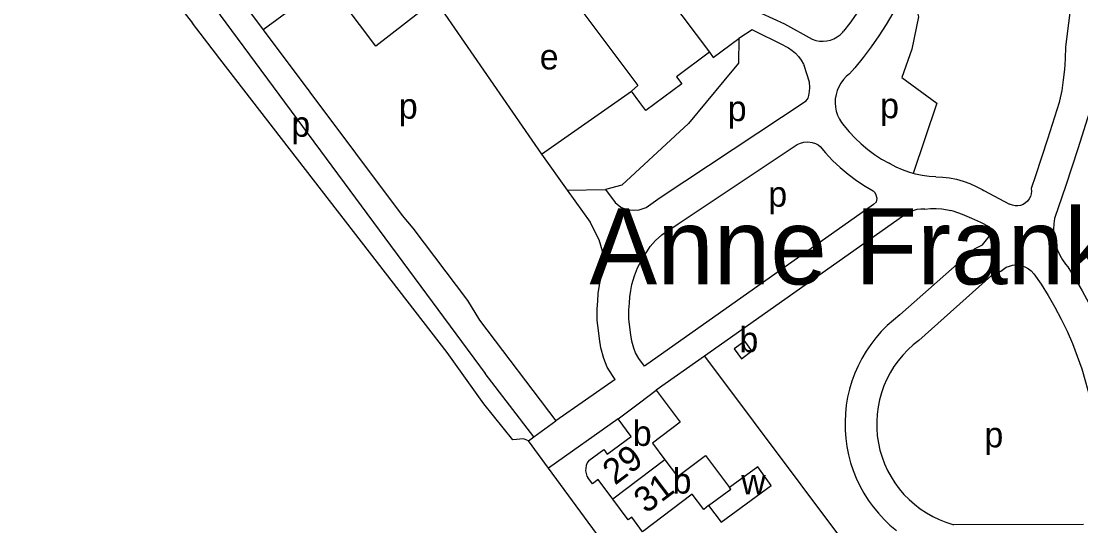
# Model space of a CAD drawing. Extents: x 160673 to 161924, y 382258 to 384145.
# Drawn here: x 161171.1 to 161338.3, y 382519.2 to 382598.9 of the extents above; entities that cross this region are included whole.
import ezdxf

# ---------------------------------------------------------------- set-up
doc = ezdxf.new("R2010")
doc.units = 0
for name, color, linetype in [('BLT_Basislijn', 7, 'Continuous'), ('BLT_Bebouwing', 7, 'Continuous'), ('BLT_Centroide', 7, 'Continuous'), ('BLT_Huisnummer', 7, 'Continuous'), ('BLT_Onderverdeling_panden', 7, 'Continuous'), ('BLT_Sport_parknaam', 7, 'Continuous')]:
    doc.layers.add(name, color=color, linetype=linetype)

msp = doc.modelspace()

# ---------------------------------------------------------------- linework, layer by layer
at = {"layer": 'BLT_Basislijn'}
for p, q in [((161236.4, 382602.22), (161253.19, 382577.89)), ((161206.62, 382601.03), (161209.25, 382597.52)), ((161202.43, 382592.91), (161198.13, 382598.56)), ((161336.39, 382598.54), (161335.89, 382594.84)), ((161291.55, 382594.97), (161286.45, 382597.53)), ((161295.52, 382589.23), (161294.67, 382591.85)), ((161253.19, 382577.89), (161267.4, 382587.83)), ((161253.19, 382577.89), (161257.25, 382572.21)), ((161257.25, 382572.21), (161263.33, 382572.31)), ((161257.25, 382572.21), (161260.89, 382567.12)), ((161263.33, 382572.31), (161264.82, 382570.23)), ((161323.03, 382572.12), (161327.09, 382569.98)), ((161305.6, 382569.91), (161269.44, 382544.38)), ((161310.2, 382568.05), (161278.95, 382546)), ((161330.89, 382558.99), (161332.07, 382557.36)), ((161278.95, 382546), (161271.3, 382540.59)), ((161278.95, 382546), (161344.75, 382458.1)), ((161252, 382533.24), (161244.3, 382543.23)), ((161264.81, 382542.29), (161255.49, 382535.78)), ((161265.31, 382536.07), (161254.33, 382528.3)), ((161252, 382533.24), (161255.49, 382535.78)), ((161251.16, 382532.63), (161252, 382533.24)), ((161254.33, 382528.3), (161251.16, 382532.63)), ((161316.36, 382443.76), (161254.33, 382528.3)), ((161318.31, 382519.37), (161338.74, 382519.43))]:
    msp.add_line(p, q, dxfattribs=at)
for points in [[(161171.3, 382640.12), (161185.2, 382622.82), (161194.99, 382609.96), (161244.3, 382543.23)], [(161171.08, 382634.13), (161172.74, 382632.12), (161190.85, 382607.88), (161198.13, 382598.56)], [(161341.17, 382612.89), (161340.34, 382611.41), (161339.58, 382609.89), (161338.9, 382608.33), (161338.29, 382606.74), (161337.75, 382605.13), (161337.29, 382603.49), (161336.91, 382601.84), (161336.61, 382600.17), (161336.39, 382598.54)], [(161308.07, 382611.12), (161307.55, 382609.44), (161306.95, 382607.78), (161306.28, 382606.15), (161305.54, 382604.55), (161304.72, 382602.99), (161303.84, 382601.47), (161302.88, 382599.98), (161301.86, 382598.55), (161300.89, 382597.3)], [(161236.4, 382602.22), (161227.08, 382594.92), (161219.48, 382605.03), (161209.25, 382597.52)], [(161310.44, 382603.65), (161309.64, 382602), (161308.65, 382600.15), (161307.59, 382598.33), (161306.46, 382596.56), (161305.26, 382594.83), (161304, 382593.15), (161302.68, 382591.51), (161301.84, 382590.54)], [(161310.44, 382603.65), (161311.44, 382602.71), (161312.41, 382600.84), (161312.73, 382599.54), (161311.65, 382594.46), (161310.07, 382589.99), (161315.63, 382585.92), (161311.89, 382574.81)], [(161287.86, 382600.13), (161291.54, 382598.43), (161295.93, 382596.02)], [(161209.25, 382597.52), (161231.19, 382568.17), (161232.88, 382566.2), (161241.53, 382554.75), (161243.44, 382551.65), (161255.49, 382535.78)], [(161284.34, 382596.15), (161284.31, 382592.26), (161282.01, 382589.44), (161276.4, 382582.73), (161265.91, 382572.98), (161263.33, 382572.31)], [(161279.71, 382593.96), (161280.32, 382593.16), (161284.34, 382596.15)], [(161286.45, 382597.53), (161284.34, 382596.15)], [(161295.93, 382596.02), (161296.49, 382595.84), (161297.07, 382595.74), (161297.66, 382595.71), (161298.24, 382595.77), (161298.81, 382595.9), (161299.36, 382596.11), (161299.88, 382596.39), (161300.35, 382596.74), (161300.77, 382597.15), (161300.89, 382597.3)], [(161291.55, 382594.97), (161292.18, 382594.65), (161292.76, 382594.25), (161293.3, 382593.8), (161293.78, 382593.28), (161294.2, 382592.71), (161294.55, 382592.1), (161294.67, 382591.85)], [(161335.89, 382594.84), (161335.84, 382592.92), (161335.74, 382591.25), (161335.57, 382589.6), (161335.31, 382587.95), (161334.98, 382586.32), (161334.91, 382586.04)], [(161251.16, 382532.63), (161250.37, 382532.92), (161248.67, 382532.79), (161244.11, 382538.46), (161238.3, 382546.58), (161202.43, 382592.91)], [(161301.84, 382590.54), (161301.32, 382590.12), (161300.86, 382589.64), (161300.46, 382589.11), (161300.13, 382588.53), (161299.87, 382587.92), (161299.69, 382587.28), (161299.58, 382586.62), (161299.55, 382585.96), (161299.61, 382585.3), (161299.74, 382584.65), (161299.95, 382584.02), (161300.23, 382583.41), (161300.58, 382582.85), (161300.92, 382582.42)], [(161294.97, 382586.31), (161295.27, 382586.72), (161295.4, 382587.14), (161295.5, 382587.77), (161295.55, 382588.41), (161295.52, 382589.23)], [(161269.72, 382569.47), (161271.95, 382571.01), (161294.97, 382586.31)], [(161334.91, 382586.04), (161333.09, 382580.24), (161331.19, 382574.46), (161330.51, 382572.46)], [(161339.69, 382584.57), (161337.86, 382578.74), (161335.95, 382572.93), (161334.17, 382567.72)], [(161300.92, 382582.42), (161301.78, 382581.39), (161302.69, 382580.41), (161303.67, 382579.49), (161304.69, 382578.63), (161305.77, 382577.83), (161306.89, 382577.1), (161308.06, 382576.43)], [(161269.44, 382544.38), (161268.59, 382545.63), (161268.05, 382546.5), (161267.76, 382547.23), (161267.45, 382548.34), (161267.29, 382549.37), (161267.15, 382550.58), (161267.01, 382551.87), (161267.01, 382553.31), (161267.07, 382554.33), (161267.13, 382555.35), (161267.28, 382556.34), (161267.48, 382557.3), (161267.88, 382558.66), (161268.36, 382559.95), (161268.97, 382561.07), (161269.59, 382562.05), (161270.37, 382563.28), (161271.21, 382564.25), (161272.21, 382565.11), (161274.76, 382566.87), (161293.58, 382579.38)], [(161293.58, 382579.38), (161294.08, 382579.63), (161294.62, 382579.79), (161295.23, 382579.8), (161295.91, 382579.72), (161296.47, 382579.57), (161296.89, 382579.35), (161297.17, 382579.11)], [(161297.17, 382579.11), (161298.03, 382578.08), (161299.15, 382576.88), (161300.34, 382575.76), (161301.59, 382574.7), (161302.91, 382573.73), (161304.28, 382572.83), (161305.57, 382572.09)], [(161311.89, 382574.81), (161311.19, 382575.01), (161310.17, 382575.38), (161309.19, 382575.82), (161308.23, 382576.33), (161308.06, 382576.43)], [(161315.45, 382574.32), (161314.37, 382574.37), (161313.3, 382574.51), (161312.24, 382574.72), (161311.89, 382574.81)], [(161315.45, 382574.32), (161316.55, 382574.26), (161317.63, 382574.12), (161318.71, 382573.91), (161319.76, 382573.61), (161320.8, 382573.24), (161321.8, 382572.79), (161322.76, 382572.28), (161323.03, 382572.12)], [(161305.6, 382569.91), (161306.06, 382570.35), (161306.18, 382570.89), (161306.04, 382571.4), (161305.87, 382571.77), (161305.57, 382572.09)], [(161330.51, 382572.46), (161330.55, 382572.03), (161330.5, 382571.6), (161330.38, 382571.18), (161330.18, 382570.8), (161329.92, 382570.46), (161329.6, 382570.17), (161329.23, 382569.94), (161328.82, 382569.79), (161328.4, 382569.72), (161327.96, 382569.72), (161327.54, 382569.8), (161327.09, 382569.98)], [(161264.82, 382570.23), (161265.71, 382569.48), (161266.63, 382569.14), (161267.68, 382569.01), (161268.63, 382569.08), (161269.72, 382569.47)], [(161313.72, 382569.21), (161313.08, 382569.2), (161312.44, 382569.11), (161311.82, 382568.95), (161311.22, 382568.71), (161310.66, 382568.39), (161310.2, 382568.05)], [(161313.72, 382569.21), (161314.61, 382569.3), (161315.51, 382569.32), (161316.4, 382569.25), (161317.28, 382569.1), (161317.79, 382568.98)], [(161323.95, 382566.32), (161322.56, 382567.06), (161321.13, 382567.73), (161319.67, 382568.33), (161318.18, 382568.86), (161317.79, 382568.98)], [(161334.17, 382567.72), (161334.05, 382566.88), (161334.01, 382566.02), (161334.06, 382565.17), (161334.18, 382564.33), (161334.38, 382563.5), (161334.66, 382562.7), (161335.01, 382561.92), (161335.43, 382561.18), (161335.93, 382560.49), (161336.26, 382560.09)], [(161264.81, 382542.29), (161264.39, 382542.91), (161263.57, 382544.24), (161263.02, 382545.61), (161262.55, 382547.28), (161262.34, 382548.69), (161262.18, 382550.02), (161262.01, 382551.61), (161262.01, 382553.46), (161262.08, 382554.64), (161262.16, 382555.86), (161262.35, 382557.21), (161262.62, 382558.52), (161263.07, 382560.81), (161262.86, 382562.54), (161262.29, 382564.33), (161260.89, 382567.12)], [(161322.79, 382563.54), (161324.08, 382565.14), (161323.95, 382566.32)], [(161309.77, 382552.48), (161321.56, 382562.95), (161322.79, 382563.54)], [(161312.75, 382548.47), (161324.25, 382558.69), (161325.71, 382559.41)], [(161325.71, 382559.41), (161326.11, 382559.74), (161326.56, 382560.01), (161327.05, 382560.21), (161327.56, 382560.34), (161328.08, 382560.38), (161328.61, 382560.35), (161329.12, 382560.23), (161329.61, 382560.04), (161330.07, 382559.78), (161330.48, 382559.45), (161330.89, 382558.99)], [(161336.26, 382560.09), (161337.43, 382558.21), (161338.54, 382556.28), (161339.58, 382554.32), (161340.55, 382552.32), (161341.45, 382550.29), (161342.27, 382548.23), (161343.02, 382546.14), (161343.69, 382544.02), (161344.28, 382541.89), (161344.44, 382541.26)], [(161332.07, 382557.36), (161333.19, 382555.55), (161334.25, 382553.71), (161335.24, 382551.83), (161336.16, 382549.91), (161337, 382547.95), (161337.77, 382545.97), (161338.47, 382543.96), (161339.09, 382541.92), (161339.59, 382540.05)], [(161309.77, 382552.48), (161308.74, 382551.67), (161307.77, 382550.8), (161306.84, 382549.87), (161305.98, 382548.88), (161305.18, 382547.84), (161304.45, 382546.76), (161303.78, 382545.63), (161303.18, 382544.47), (161302.65, 382543.27), (161302.2, 382542.04), (161301.83, 382540.79), (161301.53, 382539.51), (161301.31, 382538.22), (161301.17, 382536.92), (161301.11, 382535.61), (161301.12, 382534.3), (161301.22, 382532.99), (161301.4, 382531.7), (161301.66, 382530.41), (161301.99, 382529.15), (161302.4, 382527.9), (161302.89, 382526.69), (161303.45, 382525.5), (161304.08, 382524.36), (161304.78, 382523.25), (161305.55, 382522.19), (161306.38, 382521.17), (161307.27, 382520.21), (161308.21, 382519.31), (161309.22, 382518.46)], [(161312.75, 382548.47), (161311.85, 382547.75), (161311.01, 382546.98), (161310.22, 382546.14), (161309.49, 382545.26), (161308.83, 382544.32), (161308.23, 382543.35), (161307.7, 382542.33), (161307.24, 382541.28), (161306.86, 382540.19), (161306.55, 382539.09), (161306.33, 382537.97), (161306.18, 382536.83), (161306.11, 382535.68), (161306.12, 382534.54), (161306.21, 382533.39), (161306.38, 382532.26), (161306.63, 382531.14), (161306.95, 382530.04), (161307.36, 382528.97), (161307.83, 382527.92), (161308.38, 382526.92), (161308.99, 382525.95), (161309.68, 382525.03), (161310.42, 382524.15), (161311.22, 382523.34), (161312.08, 382522.58), (161312.99, 382521.88), (161313.95, 382521.24), (161314.95, 382520.68), (161315.98, 382520.18), (161317.05, 382519.76), (161318.14, 382519.42), (161318.31, 382519.37)]]:
    msp.add_lwpolyline(points, dxfattribs=at)
at = {"layer": 'BLT_Bebouwing'}
for p, q in [((161263.44, 382615.85), (161279.71, 382593.96)), ((161255.31, 382606.21), (161268.42, 382588.74)), ((161279.71, 382593.96), (161274.53, 382590.11)), ((161267.4, 382587.83), (161268.42, 382588.74)), ((161268.75, 382586.01), (161267.4, 382587.83))]:
    msp.add_line(p, q, dxfattribs=at)
for points in [[(161274.53, 382590.11), (161275.36, 382588.96)], [(161275.36, 382588.96), (161269.68, 382584.76), (161268.75, 382586.01)], [(161265.31, 382536.07), (161268.7, 382538.63), (161271.3, 382540.59)], [(161271.3, 382540.59), (161275.1, 382535.58), (161270.7, 382532.25), (161272.69, 382529.62)], [(161260.68, 382529.48), (161263.04, 382531.24), (161263.58, 382530.5), (161267.36, 382533.31), (161265.31, 382536.07)], [(161260.68, 382529.48), (161260.44, 382529.12), (161260.27, 382528.73), (161260.18, 382528.31), (161260.17, 382527.88), (161260.24, 382527.46), (161260.38, 382527.05), (161260.52, 382526.8)], [(161272.69, 382529.62), (161274.68, 382526.99), (161279.07, 382530.31), (161282.89, 382525.26)], [(161279.59, 382522.38), (161281.55, 382519.78), (161289.44, 382525.57), (161287.33, 382528.51), (161282.89, 382525.26)], [(161264.46, 382523.4), (161262.17, 382526.48), (161261.26, 382525.8), (161260.52, 382526.8)], [(161279.59, 382522.38), (161278.81, 382521.78), (161277, 382524.18), (161269.17, 382518.26), (161267.44, 382520.55), (161266.89, 382520.14), (161264.46, 382523.4)]]:
    msp.add_lwpolyline(points, dxfattribs=at)
msp.add_lwpolyline([(161285.28, 382548.36), (161283.62, 382547.13), (161284.78, 382545.57), (161286.43, 382546.8)], close=True, dxfattribs=at)
at = {"layer": 'BLT_Onderverdeling_panden'}
msp.add_line((161272.69, 382529.62), (161264.46, 382523.4), dxfattribs=at)
msp.add_lwpolyline([(161279.59, 382522.38), (161283.1, 382524.98), (161282.89, 382525.26)], dxfattribs=at)

# ---------------------------------------------------------------- texts
at = {"layer": 'BLT_Centroide'}
for s, p in [('e', (161252.93, 382591.25)), ('p', (161230.69, 382583.48)), ('p', (161282.6, 382583.1)), ('p', (161306.66, 382583.55)), ('p', (161213.72, 382580.62)), ('p', (161289, 382569.58)), ('b', (161284.45, 382546.6)), ('b', (161267.62, 382531.81)), ('p', (161323.12, 382531.58)), ('b', (161273.9, 382524.28)), ('w', (161284.73, 382524.16))]:
    msp.add_text(s, height=4, dxfattribs=at).set_placement(p)
at = {"layer": 'BLT_Huisnummer'}
for s, rotation, p in [('29', 37.0887, (161264.8, 382525.51)), ('31', 37.0811, (161269.72, 382521.02))]:
    msp.add_text(s, height=4, rotation=rotation, dxfattribs=at).set_placement(p)
at = {"layer": 'BLT_Sport_parknaam'}
msp.add_text('Anne Frankplantsoen', height=12, dxfattribs=at).set_placement((161260.77, 382557.31))

doc.saveas('drawing.dxf')
